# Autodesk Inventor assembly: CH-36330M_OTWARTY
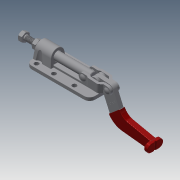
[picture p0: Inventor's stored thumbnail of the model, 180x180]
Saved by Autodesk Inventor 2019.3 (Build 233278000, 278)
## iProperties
Company: Î¢ÈíÖÐ¹ú
Created: 2012-09
Part Number: CH-36330M_OTWARTY
Material: Ogólny
Description: STEP AP203
Document SubType Name: Assembly
Designer: CADENGINEERING4
Sending System: SolidWorks 2010
Preprocessor: SwSTEP 2.0
Title: CH-36330M.STEP
Author: Î¢ÈíÓÃ»§
Revision Number: ÈÎºÎ
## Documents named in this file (11)
- D:\Vault_2016\Projekty\STRONA\Push-pull clamp\CH-36330M\CH-36330M_OTWARTY.iam
- D:\Vault_2016\Projekty\STRONA\Push-pull clamp\CH-36330M\CH-36330M-01 BASE.ipt
- D:\Vault_2016\Projekty\STRONA\Push-pull clamp\CH-36330M\CH-36330M-02 CREST STALK.ipt
- D:\Vault_2016\Projekty\STRONA\Push-pull clamp\CH-36330M\M10 Nut.ipt
- D:\Vault_2016\Projekty\STRONA\Push-pull clamp\CH-36330M\CH-36330M-07.ipt
- D:\Vault_2016\Projekty\STRONA\Push-pull clamp\CH-36330M\CH-36330M-03 HANDLE.ipt
- D:\Vault_2016\Projekty\STRONA\Push-pull clamp\CH-36330M\CH-36330M-04 CONNECTING-PLATE.ipt
- D:\Vault_2016\Projekty\STRONA\Push-pull clamp\CH-36330M\CH-36330M-08.ipt
- D:\Vault_2016\Projekty\STRONA\Push-pull clamp\CH-36330M\CH-36330M-05.ipt
- D:\Vault_2016\Projekty\STRONA\Push-pull clamp\CH-36330M\CH-36330M-06.ipt
- D:\Vault_2016\Projekty\STRONA\Push-pull clamp\CH-36330M\CH-SA-105015 SPINDLE SUPPLIED.ipt
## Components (11 placed, 11 different names)
1. CH-36330M-01 BASE_1 — Zestawiające:6, Zestawiające:15, Równoległe:2, Zestawiające:19, Zestawiające:20
2. CH-36330M-02 CREST STALK_2 — Zestawiające:3, Zestawiające:4, Zestawiające:12, Zestawiające:13, Zestawiające:19
3. M10 Nut_3 — Zestawiające:1, Zestawiające:2, Zestawiające:3
4. CH-36330M-07_4 — Zestawiające:14, Zestawiające:18
5. CH-36330M-03 HANDLE_5 — Zestawiające:5, Równoległe:1, Zestawiające:6, Zestawiające:7, Zestawiające:8, Zestawiające:15, Zestawiające:16
6. CH-36330M-04 CONNECTING-PLATE_6 — Zestawiające:7, Zestawiające:9, Zestawiające:10
7. CH-36330M-04 CONNECTING-PLATE_7 — Zestawiające:8, Zestawiające:9, Zestawiające:10, Zestawiające:11, Zestawiające:12, Zestawiające:17, Zestawiające:18, Zestawiające:20
8. CH-36330M-08_8 — Zestawiające:13, Zestawiające:17
9. CH-36330M-05_9 — Zestawiające:5, Równoległe:1, Zestawiające:11, Zestawiające:14
10. CH-36330M-06_10 — Zestawiające:16, Równoległe:2
11. CH-SA-105015 SPINDLE SUPPLIED_11 — Zestawiające:1, Zestawiające:2, Zestawiające:4
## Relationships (22: Mate 20, Flush 2)
- Zestawiające:1 [Mate]: M10 Nut_3 ↔ CH-SA-105015 SPINDLE SUPPLIED_11
- Zestawiające:2 [Mate]: M10 Nut_3 ↔ CH-SA-105015 SPINDLE SUPPLIED_11
- Zestawiające:3 [Mate]: CH-36330M-02 CREST STALK_2 ↔ M10 Nut_3
- Zestawiające:4 [Mate]: CH-36330M-02 CREST STALK_2 ↔ CH-SA-105015 SPINDLE SUPPLIED_11
- Zestawiające:5 [Mate]: CH-36330M-03 HANDLE_5 ↔ CH-36330M-05_9
- Równoległe:1 [Flush]: CH-36330M-03 HANDLE_5 ↔ CH-36330M-05_9
- Zestawiające:6 [Mate]: CH-36330M-01 BASE_1 ↔ CH-36330M-03 HANDLE_5
- Zestawiające:7 [Mate]: CH-36330M-03 HANDLE_5 ↔ CH-36330M-04 CONNECTING-PLATE_6
- Zestawiające:8 [Mate]: CH-36330M-03 HANDLE_5 ↔ CH-36330M-04 CONNECTING-PLATE_7
- Zestawiające:9 [Mate]: CH-36330M-04 CONNECTING-PLATE_6 ↔ CH-36330M-04 CONNECTING-PLATE_7
- Zestawiające:10 [Mate]: CH-36330M-04 CONNECTING-PLATE_6 ↔ CH-36330M-04 CONNECTING-PLATE_7
- Zestawiające:11 [Mate]: CH-36330M-04 CONNECTING-PLATE_7 ↔ CH-36330M-05_9
- Zestawiające:12 [Mate]: CH-36330M-02 CREST STALK_2 ↔ CH-36330M-04 CONNECTING-PLATE_7
- Zestawiające:13 [Mate]: CH-36330M-02 CREST STALK_2 ↔ CH-36330M-08_8
- Zestawiające:14 [Mate]: CH-36330M-07_4 ↔ CH-36330M-05_9
- Zestawiające:15 [Mate]: CH-36330M-01 BASE_1 ↔ CH-36330M-03 HANDLE_5
- Zestawiające:16 [Mate]: CH-36330M-03 HANDLE_5 ↔ CH-36330M-06_10
- Równoległe:2 [Flush]: CH-36330M-01 BASE_1 ↔ CH-36330M-06_10
- Zestawiające:17 [Mate]: CH-36330M-04 CONNECTING-PLATE_7 ↔ CH-36330M-08_8
- Zestawiające:18 [Mate]: CH-36330M-07_4 ↔ CH-36330M-04 CONNECTING-PLATE_7
- Zestawiające:19 [Mate]: CH-36330M-01 BASE_1 ↔ CH-36330M-02 CREST STALK_2
- Zestawiające:20 [Mate]: CH-36330M-01 BASE_1 ↔ CH-36330M-04 CONNECTING-PLATE_7
